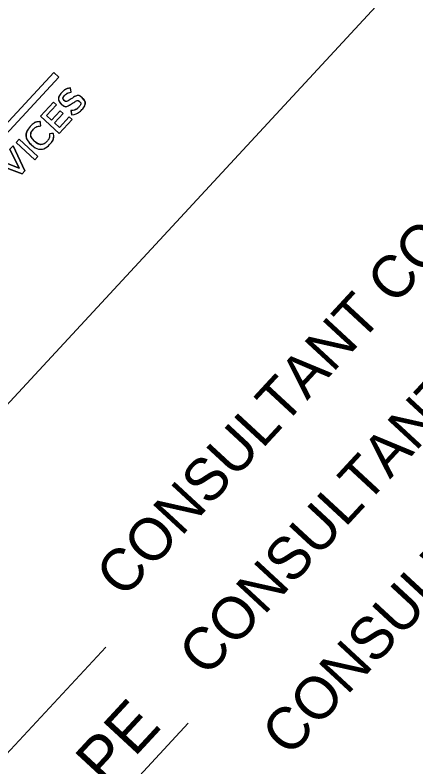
# Model space of a CAD drawing. Extents: x 1766669 to 1770980, y 998119 to 1002502.
# Drawn here: x 1769807 to 1769938.3, y 999842.6 to 1000088.8 of the extents above; entities that cross this region are included whole.
import ezdxf

# ---------------------------------------------------------------- set-up
doc = ezdxf.new("R2010")
doc.units = 0
doc.layers.add('Default Symbol CELL', color=7, linetype='Continuous')

msp = doc.modelspace()

# ---------------------------------------------------------------- linework, layer by layer
at = {"layer": 'Default Symbol CELL'}
for p, q in [((1769610.25, 999751.61), (1770028.19, 1000202.97)), ((1769825.43, 1000063.62), (1769825.15, 1000064.96)), ((1769823.08, 1000060.86), (1769823.06, 1000060.87)), ((1769829.03, 1000061.71), (1769829.01, 1000061.72)), ((1769822.16, 1000059.71), (1769822.18, 1000059.69)), ((1769828.12, 1000060.55), (1769828.14, 1000060.53)), ((1769825.31, 1000057.54), (1769825.49, 1000056.17)), ((1769815.44, 1000052.53), (1769815.28, 1000053.96)), ((1769819.63, 1000050.02), (1769818.29, 1000049.98)), ((1769812.36, 1000046.35), (1769812.38, 1000046.33)), ((1769813.4, 1000047.48), (1769813.39, 1000047.49)), ((1769667.24, 999699.33), (1769836.77, 999881.92)), ((1769694.23, 999674.46), (1769863.71, 999857))]:
    msp.add_line(p, q, dxfattribs=at)
for points in [[(1769821.38, 1000068.54), (1769662.96, 999897.34), (1769661.33, 999898.85), (1769819.74, 1000070.05), (1769821.38, 1000068.54)], [(1769819.74, 1000070.05), (1769661.33, 999898.85), (1769662.96, 999897.34), (1769821.38, 1000068.54), (1769819.74, 1000070.05)], [(1769815.36, 1000055.75), (1769819.56, 1000060.29), (1769820.53, 1000059.4), (1769817.32, 1000055.93), (1769818.91, 1000054.45), (1769821.76, 1000057.53), (1769822.72, 1000056.64), (1769819.88, 1000053.56), (1769821.53, 1000052.04), (1769824.78, 1000055.55), (1769825.74, 1000054.65), (1769821.5, 1000050.07), (1769815.36, 1000055.75)], [(1769821.5, 1000050.07), (1769825.74, 1000054.65), (1769824.78, 1000055.55), (1769821.53, 1000052.04), (1769819.88, 1000053.56), (1769822.72, 1000056.64), (1769821.76, 1000057.53), (1769818.91, 1000054.45), (1769817.32, 1000055.93), (1769820.53, 1000059.4), (1769819.56, 1000060.29), (1769815.36, 1000055.75), (1769821.5, 1000050.07)], [(1769800.81, 1000040.03), (1769801.92, 1000041.22), (1769808.35, 1000038.7), (1769805.33, 1000044.91), (1769806.41, 1000046.07), (1769810.24, 1000037.81), (1769809.36, 1000036.86), (1769800.81, 1000040.03)], [(1769809.36, 1000036.86), (1769810.24, 1000037.81), (1769806.41, 1000046.07), (1769805.33, 1000044.91), (1769808.35, 1000038.7), (1769801.92, 1000041.22), (1769800.81, 1000040.03), (1769809.36, 1000036.86)], [(1769807.35, 1000047.1), (1769808.35, 1000048.18), (1769814.49, 1000042.49), (1769813.49, 1000041.42), (1769807.35, 1000047.1)], [(1769813.49, 1000041.42), (1769814.49, 1000042.49), (1769808.35, 1000048.18), (1769807.35, 1000047.1), (1769813.49, 1000041.42)]]:
    msp.add_lwpolyline(points, dxfattribs=at)
for points in [[(1769825.15, 1000064.96), (1769824.07, 1000064.8), (1769823.14, 1000064.34), (1769822.32, 1000063.45), (1769821.19, 1000062.23), (1769821.11, 1000060.68), (1769822.16, 1000059.71)], [(1769825.49, 1000056.17), (1769825.49, 1000056.17), (1769825.31, 1000057.54), (1769825.31, 1000057.54), (1769826.37, 1000057.65), (1769827.21, 1000057.98), (1769827.9, 1000058.73), (1769828.52, 1000059.4), (1769828.59, 1000060.11), (1769828.14, 1000060.53), (1769828.14, 1000060.53), (1769828.12, 1000060.55), (1769828.12, 1000060.55), (1769827.68, 1000060.95), (1769827.22, 1000060.93), (1769825.9, 1000060.03), (1769824.38, 1000059.02), (1769823.31, 1000058.64), (1769822.18, 1000059.69), (1769822.18, 1000059.69), (1769822.16, 1000059.71), (1769822.16, 1000059.71), (1769821.11, 1000060.68), (1769821.19, 1000062.23), (1769822.32, 1000063.45), (1769823.14, 1000064.34), (1769824.07, 1000064.8), (1769825.15, 1000064.96), (1769825.15, 1000064.96), (1769825.43, 1000063.62), (1769825.43, 1000063.62), (1769824.51, 1000063.45), (1769823.78, 1000063.1), (1769823.26, 1000062.54), (1769822.67, 1000061.91), (1769822.66, 1000061.24), (1769823.06, 1000060.87), (1769823.06, 1000060.87), (1769823.08, 1000060.86), (1769823.08, 1000060.86), (1769823.55, 1000060.42), (1769824.02, 1000060.5), (1769825.4, 1000061.42), (1769826.91, 1000062.43), (1769827.99, 1000062.66), (1769829.01, 1000061.72), (1769829.01, 1000061.72), (1769829.03, 1000061.71), (1769829.03, 1000061.71), (1769830.18, 1000060.64), (1769830.03, 1000059.11), (1769828.84, 1000057.82), (1769827.97, 1000056.88), (1769826.83, 1000056.3), (1769825.49, 1000056.17)], [(1769823.06, 1000060.87), (1769822.66, 1000061.24), (1769822.67, 1000061.91), (1769823.26, 1000062.54), (1769823.78, 1000063.1), (1769824.51, 1000063.45), (1769825.43, 1000063.62)], [(1769822.18, 1000059.69), (1769823.31, 1000058.64), (1769824.38, 1000059.02), (1769825.9, 1000060.03), (1769827.22, 1000060.93), (1769827.68, 1000060.95), (1769828.12, 1000060.55)], [(1769829.01, 1000061.72), (1769827.99, 1000062.66), (1769826.91, 1000062.43), (1769825.4, 1000061.42), (1769824.02, 1000060.5), (1769823.55, 1000060.42), (1769823.08, 1000060.86)], [(1769825.49, 1000056.17), (1769826.83, 1000056.3), (1769827.97, 1000056.88), (1769828.84, 1000057.82), (1769830.03, 1000059.11), (1769830.18, 1000060.64), (1769829.03, 1000061.71)], [(1769828.14, 1000060.53), (1769828.59, 1000060.11), (1769828.52, 1000059.4), (1769827.9, 1000058.73), (1769827.21, 1000057.98), (1769826.37, 1000057.65), (1769825.31, 1000057.54)], [(1769812.38, 1000046.33), (1769812.38, 1000046.33), (1769812.36, 1000046.35), (1769812.36, 1000046.35), (1769810.61, 1000047.96), (1769810.39, 1000050.59), (1769812.11, 1000052.45), (1769813.15, 1000053.58), (1769814.18, 1000053.9), (1769815.28, 1000053.96), (1769815.28, 1000053.96), (1769815.44, 1000052.53), (1769815.44, 1000052.53), (1769814.53, 1000052.47), (1769813.74, 1000052.22), (1769813.09, 1000051.52), (1769812.01, 1000050.36), (1769812.18, 1000048.61), (1769813.39, 1000047.49), (1769813.39, 1000047.49), (1769813.4, 1000047.48), (1769813.4, 1000047.48), (1769814.61, 1000046.37), (1769816.37, 1000046.31), (1769817.45, 1000047.49), (1769818.15, 1000048.24), (1769818.3, 1000049), (1769818.29, 1000049.98), (1769818.29, 1000049.98), (1769819.63, 1000050.02), (1769819.63, 1000050.02), (1769819.71, 1000048.77), (1769819.48, 1000047.68), (1769818.42, 1000046.53), (1769816.77, 1000044.74), (1769814.14, 1000044.7), (1769812.38, 1000046.33)], [(1769815.28, 1000053.96), (1769814.18, 1000053.9), (1769813.15, 1000053.58), (1769812.11, 1000052.45), (1769810.39, 1000050.59), (1769810.61, 1000047.96), (1769812.36, 1000046.35)], [(1769813.39, 1000047.49), (1769812.18, 1000048.61), (1769812.01, 1000050.36), (1769813.09, 1000051.52), (1769813.74, 1000052.22), (1769814.53, 1000052.47), (1769815.44, 1000052.53)], [(1769812.38, 1000046.33), (1769814.14, 1000044.7), (1769816.77, 1000044.74), (1769818.42, 1000046.53), (1769819.48, 1000047.68), (1769819.71, 1000048.77), (1769819.63, 1000050.02)], [(1769818.29, 1000049.98), (1769818.3, 1000049), (1769818.15, 1000048.24), (1769817.45, 1000047.49), (1769816.37, 1000046.31), (1769814.61, 1000046.37), (1769813.4, 1000047.48)]]:
    msp.add_open_spline(points, degree=3, dxfattribs=at)

# ---------------------------------------------------------------- texts
for s, height, p in [('CONSULTANT CONTACT #1', 13.8548, (1769842.54, 999897.47)), ('CONSULTANT CONTACT #2', 13.8548, (1769869.65, 999871.69)), ('CONSULTANT CONTACT #3', 13.8548, (1769896.85, 999845.52)), ('SPENCER MERRITT, PE', 15.2403, (1769696.93, 999684.32))]:
    msp.add_text(s, height=height, rotation=47.237, dxfattribs=at).set_placement(p)

doc.saveas('drawing.dxf')
